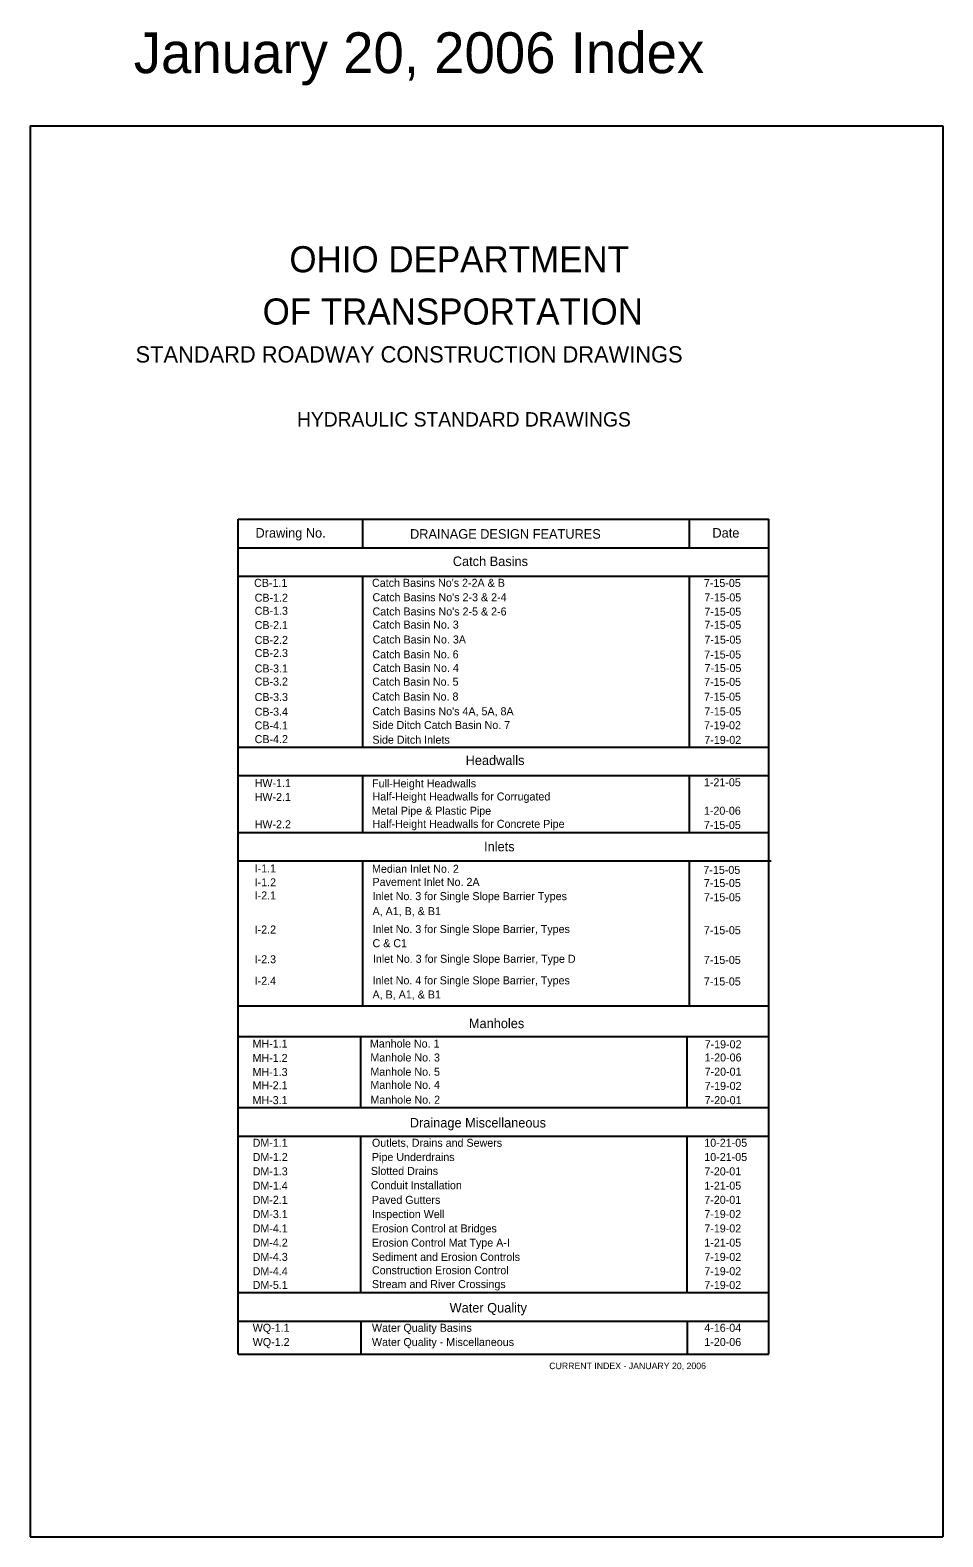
# Model space of a CAD drawing. Extents: x 146 to 619, y 56 to 2134.
# Drawn here: x 597.17 to 619.17, y 2097.9 to 2134.21 of the extents above; entities that cross this region are included whole.
import ezdxf

# ---------------------------------------------------------------- set-up
doc = ezdxf.new("R2010")
doc.units = 0
doc.layers.add('Level 1', color=7, linetype='Continuous')

msp = doc.modelspace()

# ---------------------------------------------------------------- linework, layer by layer
at = {"layer": 'Level 1'}
for p, q in [((597.168, 2131.9), (619.168, 2131.9)), ((597.168, 2131.9), (597.168, 2097.9)), ((619.168, 2131.9), (619.168, 2097.9)), ((602.185, 2102.304), (602.185, 2122.419)), ((602.185, 2122.419), (614.974, 2122.419)), ((602.185, 2122.419), (602.185, 2122.419)), ((605.188, 2121.733), (605.188, 2122.419)), ((613.058, 2121.733), (613.058, 2122.419)), ((614.974, 2102.304), (614.974, 2122.419)), ((614.974, 2122.419), (614.974, 2122.419)), ((602.185, 2121.733), (614.974, 2121.733)), ((602.185, 2121.047), (614.974, 2121.047)), ((605.188, 2116.932), (605.188, 2121.047)), ((613.058, 2116.932), (613.058, 2121.047)), ((602.185, 2116.932), (614.974, 2116.932)), ((602.185, 2116.246), (614.974, 2116.246)), ((605.188, 2114.872), (605.188, 2116.246)), ((613.058, 2114.872), (613.058, 2116.246)), ((602.185, 2114.874), (614.974, 2114.874)), ((602.185, 2114.188), (614.974, 2114.188)), ((602.237, 2114.188), (615.026, 2114.188)), ((605.188, 2114.188), (605.188, 2114.192)), ((605.188, 2110.695), (605.188, 2114.188)), ((613.058, 2114.188), (613.058, 2114.189)), ((613.058, 2110.695), (613.058, 2114.188)), ((602.185, 2110.695), (614.974, 2110.695)), ((602.185, 2109.958), (614.974, 2109.958)), ((605.137, 2108.243), (605.137, 2109.958)), ((613.007, 2108.266), (613.007, 2109.958)), ((605.137, 2108.243), (605.137, 2109.272)), ((613.007, 2108.243), (613.007, 2109.272)), ((602.185, 2108.243), (614.974, 2108.243)), ((602.185, 2107.557), (614.974, 2107.557)), ((605.137, 2106.185), (605.137, 2107.557)), ((613.007, 2106.185), (613.007, 2107.557)), ((613.007, 2104.826), (613.007, 2107.536)), ((605.137, 2104.283), (605.137, 2107.027)), ((605.137, 2103.785), (605.137, 2105.156)), ((613.007, 2103.784), (613.007, 2105.177)), ((602.185, 2103.785), (614.974, 2103.785)), ((602.185, 2103.099), (614.974, 2103.099)), ((605.137, 2103.099), (605.137, 2102.304)), ((613.007, 2103.098), (613.007, 2102.303)), ((602.185, 2102.304), (614.974, 2102.304)), ((597.168, 2097.9), (619.168, 2097.9))]:
    msp.add_line(p, q, dxfattribs=at)

# ---------------------------------------------------------------- texts
for s, height, p in [('January 20, 2006 Index', 0.98375, (599.666, 2133.169)), ('OHIO DEPARTMENT', 0.6296, (603.417, 2128.37)), ('OF TRANSPORTATION', 0.6296, (602.772, 2127.111)), ('STANDARD ROADWAY CONSTRUCTION DRAWINGS', 0.3935, (599.71, 2126.196)), ('HYDRAULIC STANDARD DRAWINGS', 0.34707, (603.601, 2124.653)), ('Drawing No.', 0.23, (602.6, 2121.977)), ('DRAINAGE DESIGN FEATURES', 0.23, (606.325, 2121.951)), ('Date', 0.23, (613.614, 2121.977)), ('Catch Basins', 0.23, (607.356, 2121.292)), ('CB-1.1', 0.1928, (602.566, 2120.791)), ("Catch Basins No's 2-2A & B", 0.1928, (605.409, 2120.792)), ('7-15-05', 0.1928, (613.408, 2120.788)), ('CB-1.2', 0.1928, (602.58, 2120.433)), ("Catch Basins No's 2-3 & 2-4", 0.1928, (605.421, 2120.444)), ('7-15-05', 0.1928, (613.419, 2120.44)), ('CB-1.3', 0.1928, (602.58, 2120.118)), ("Catch Basins No's 2-5 & 2-6", 0.1928, (605.421, 2120.101)), ('7-15-05', 0.1928, (613.419, 2120.097)), ('CB-2.1', 0.1928, (602.58, 2119.774)), ('Catch Basin No. 3', 0.1928, (605.421, 2119.785)), ('7-15-05', 0.1928, (613.419, 2119.78)), ('CB-2.2', 0.1928, (602.58, 2119.416)), ('Catch Basin No. 3A', 0.1928, (605.423, 2119.426)), ('7-15-05', 0.1928, (613.421, 2119.422)), ('CB-2.3', 0.1928, (602.58, 2119.1)), ('Catch Basin No. 6', 0.1928, (605.418, 2119.068)), ('7-15-05', 0.1928, (613.416, 2119.064)), ('CB-3.1', 0.1928, (602.58, 2118.728)), ('Catch Basin No. 4', 0.1928, (605.424, 2118.742)), ('7-15-05', 0.1928, (613.422, 2118.738)), ('CB-3.2', 0.1928, (602.58, 2118.413)), ('Catch Basin No. 5', 0.1928, (605.415, 2118.409)), ('7-15-05', 0.1928, (613.414, 2118.405)), ('CB-3.3', 0.1928, (602.58, 2118.04)), ('Catch Basin No. 8', 0.1928, (605.414, 2118.051)), ('7-15-05', 0.1928, (613.412, 2118.047)), ('CB-3.4', 0.1928, (602.58, 2117.686)), ("Catch Basins No's 4A, 5A, 8A", 0.1928, (605.419, 2117.697)), ('7-15-05', 0.1928, (613.418, 2117.693)), ('CB-4.1', 0.1928, (602.58, 2117.354)), ('Side Ditch Catch Basin No. 7', 0.1928, (605.414, 2117.366)), ('7-19-02', 0.1928, (613.412, 2117.361)), ('CB-4.2', 0.1928, (602.58, 2117.025)), ('Side Ditch Inlets', 0.1928, (605.419, 2117.011)), ('7-19-02', 0.1928, (613.418, 2117.007)), ('Headwalls', 0.23, (607.665, 2116.497)), ('HW-1.1', 0.1928, (602.58, 2115.967)), ('Full-Height Headwalls', 0.1928, (605.409, 2115.959)), ('1-21-05', 0.1928, (613.408, 2115.986)), ('HW-2.1', 0.1928, (602.58, 2115.632)), ('Half-Height Headwalls for Corrugated ', 0.1928, (605.421, 2115.643)), ('       Metal Pipe & Plastic Pipe', 0.1928, (604.898, 2115.3)), ('Half-Height Headwalls for Concrete Pipe', 0.1928, (605.421, 2114.984)), ('1-20-06', 0.1928, (613.408, 2115.3)), ('HW-2.2', 0.1928, (602.58, 2114.974)), ('7-15-05', 0.1928, (613.408, 2114.957)), ('Inlets', 0.23, (608.11, 2114.418)), ('I-1.1', 0.1928, (602.58, 2113.91)), ('Median Inlet No. 2', 0.1928, (605.409, 2113.901)), ('I-1.2', 0.1928, (602.58, 2113.574)), ('Pavement Inlet No. 2A', 0.1928, (605.421, 2113.585)), ('7-15-05', 0.1928, (613.396, 2113.874)), ('7-15-05', 0.1928, (613.408, 2113.558)), ('I-2.1', 0.1928, (602.58, 2113.259)), ('Inlet No. 3 for Single Slope Barrier Types ', 0.1928, (605.421, 2113.242)), ('7-15-05', 0.1928, (613.408, 2113.215)), ('A, A1, B, & B1', 0.1928, (605.421, 2112.881)), ('I-2.2', 0.1928, (602.58, 2112.438)), ('Inlet No. 3 for Single Slope Barrier, Types', 0.1928, (605.421, 2112.449)), ('C & C1', 0.1928, (605.421, 2112.108)), ('7-15-05', 0.1928, (613.407, 2112.422)), ('I-2.3', 0.1928, (602.58, 2111.721)), ('Inlet No. 3 for Single Slope Barrier, Type D', 0.1928, (605.429, 2111.732)), ('7-15-05', 0.1928, (613.407, 2111.705)), ('I-2.4', 0.1928, (602.58, 2111.202)), ('Inlet No. 4 for Single Slope Barrier, Types', 0.1928, (605.421, 2111.213)), ('7-15-05', 0.1928, (613.407, 2111.186)), ('A, B, A1, & B1', 0.1928, (605.421, 2110.872)), ('Manholes', 0.23, (607.744, 2110.158)), ('MH-1.1', 0.1928, (602.528, 2109.687)), ('Manhole No. 1', 0.1928, (605.358, 2109.69)), ('7-19-02', 0.1928, (613.426, 2109.672)), ('MH-1.2', 0.1928, (602.528, 2109.343)), ('Manhole No. 3', 0.1928, (605.369, 2109.354)), ('1-20-06', 0.1928, (613.426, 2109.355)), ('MH-1.3', 0.1928, (602.528, 2109.003)), ('Manhole No. 5', 0.1928, (605.369, 2109.011)), ('7-20-01', 0.1928, (613.426, 2109.012)), ('MH-2.1', 0.1928, (602.528, 2108.684)), ('Manhole No. 4', 0.1928, (605.369, 2108.695)), ('7-19-02', 0.1928, (613.426, 2108.669)), ('MH-3.1', 0.1928, (602.528, 2108.326)), ('Manhole No. 2', 0.1928, (605.371, 2108.337)), ('7-20-01', 0.1928, (613.426, 2108.326)), ('Drainage Miscellaneous', 0.23, (606.319, 2107.764)), ('DM-1.1', 0.1928, (602.532, 2107.299)), ('Outlets, Drains and Sewers', 0.1928, (605.407, 2107.299)), ('10-21-05', 0.1928, (613.418, 2107.299)), ('DM-1.2', 0.1928, (602.532, 2106.956)), ('Slotted Drains', 0.1928, (605.381, 2106.621)), ('Pipe Underdrains', 0.1928, (605.407, 2106.956)), ('10-21-05', 0.1928, (613.418, 2106.956)), ('DM-1.3', 0.1928, (602.532, 2106.611)), ('DM-1.4', 0.1928, (602.532, 2106.266)), ('Conduit Installation', 0.1928, (605.381, 2106.276)), ('7-20-01', 0.1928, (613.418, 2106.611)), ('1-21-05', 0.1928, (613.418, 2106.266)), ('DM-2.1', 0.1928, (602.532, 2105.924)), ('Paved Gutters', 0.1928, (605.407, 2105.924)), ('7-20-01', 0.1928, (613.418, 2105.924)), ('DM-3.1', 0.1928, (602.532, 2105.581)), ('Inspection Well', 0.1928, (605.407, 2105.581)), ('7-19-02', 0.1928, (613.418, 2105.581)), ('DM-4.1', 0.1928, (602.532, 2105.236)), ('Erosion Control at Bridges', 0.1928, (605.407, 2105.236)), ('7-19-02', 0.1928, (613.418, 2105.236)), ('DM-4.2', 0.1928, (602.532, 2104.893)), ('Erosion Control Mat Type A-I', 0.1928, (605.407, 2104.893)), ('1-21-05', 0.1928, (613.418, 2104.893)), ('DM-4.3', 0.1928, (602.532, 2104.549)), ('Sediment and Erosion Controls', 0.1928, (605.407, 2104.549)), ('7-19-02', 0.1928, (613.418, 2104.549)), ('DM-4.4', 0.1928, (602.532, 2104.204)), ('Construction Erosion Control', 0.1928, (605.407, 2104.227)), ('7-19-02', 0.1928, (613.418, 2104.204)), ('DM-5.1', 0.1928, (602.532, 2103.873)), ('Stream and River Crossings', 0.1928, (605.407, 2103.894)), ('7-19-02', 0.1928, (613.418, 2103.873)), ('Water Quality', 0.23, (607.279, 2103.306)), ('WQ-1.1', 0.1928, (602.533, 2102.841)), ('Water Quality Basins', 0.1928, (605.407, 2102.841)), ('4-16-04', 0.1928, (613.418, 2102.841)), ('WQ-1.2', 0.1928, (602.533, 2102.498)), ('Water Quality - Miscellaneous', 0.1928, (605.407, 2102.498)), ('1-20-06', 0.1928, (613.418, 2102.498)), ('CURRENT INDEX - JANUARY 20, 2006', 0.1574, (609.68, 2101.941))]:
    msp.add_text(s, height=height, dxfattribs=at).set_placement(p)

doc.saveas('drawing.dxf')
